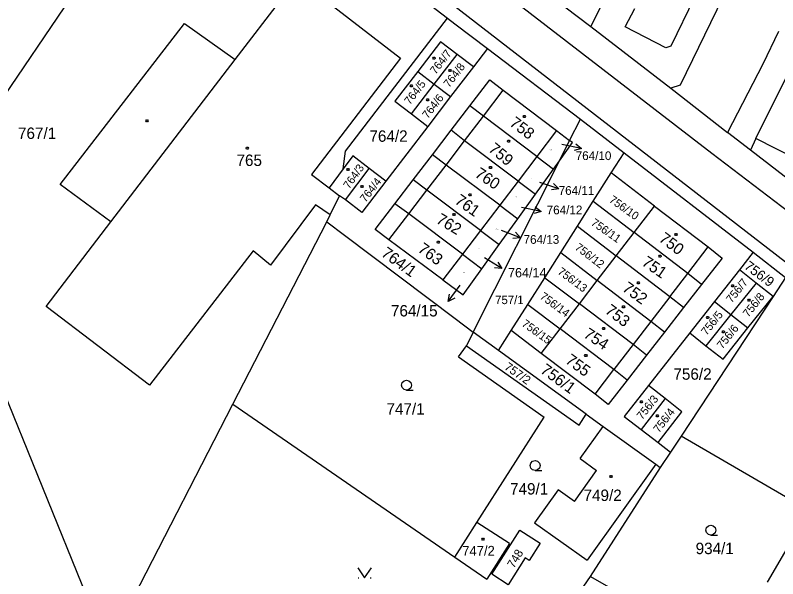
# Model space of a CAD drawing. Extents: x -621797 to -620972, y -1175539 to -1174697.
# Drawn here: x -621205.7 to -621092, y -1175296.1 to -1175212.1 of the extents above; entities that cross this region are included whole.
import ezdxf

# ---------------------------------------------------------------- set-up
doc = ezdxf.new("R2010")
doc.units = 0
for name, color, linetype in [('INZ mimo EON - nadz', 7, 'Continuous'), ('Rozvod plynu EON', 7, 'Continuous'), ('SDEL EON', 7, 'Continuous'), ('SDEL EON - popis', 7, 'Continuous'), ('Silnoproud EON', 7, 'Continuous'), ('Silnoproud EON - popis', 7, 'Continuous')]:
    doc.layers.add(name, color=color, linetype=linetype)

msp = doc.modelspace()

# ---------------------------------------------------------------- linework, layer by layer
at = {"layer": 'INZ mimo EON - nadz'}
for p, q in [((-621121.266, -1175232.014), (-621124.2, -1175231.39)), ((-621124.643, -1175238.016), (-621127.48, -1175237.04)), ((-621127.275, -1175241.364), (-621130.22, -1175240.79)), ((-621130.379, -1175245.295), (-621133.18, -1175244.22)), ((-621133.149, -1175249.836), (-621135.72, -1175248.29)), ((-621141.124, -1175254.787), (-621139.36, -1175252.36))]:
    msp.add_line(p, q, dxfattribs=at)
for points in [[(-621122.14, -1175231.317), (-621121.266, -1175232.014), (-621122.348, -1175232.295)], [(-621125.426, -1175237.218), (-621124.643, -1175238.016), (-621125.751, -1175238.164)], [(-621128.161, -1175240.682), (-621127.275, -1175241.364), (-621128.353, -1175241.663)], [(-621131.134, -1175244.47), (-621130.379, -1175245.295), (-621131.492, -1175245.403)], [(-621133.748, -1175248.892), (-621133.149, -1175249.836), (-621134.264, -1175249.749)], [(-621140.132, -1175254.272), (-621141.124, -1175254.787), (-621140.94, -1175253.684)]]:
    msp.add_lwpolyline(points, dxfattribs=at)
at = {"layer": 'Rozvod plynu EON'}
for points in [[(-621143.16, -1175218.41), (-621143.07, -1175218.56), (-621143.16, -1175218.71), (-621143.34, -1175218.71), (-621143.43, -1175218.56), (-621143.34, -1175218.41)], [(-621140.79, -1175220.22), (-621140.7, -1175220.37), (-621140.79, -1175220.52), (-621140.97, -1175220.52), (-621141.06, -1175220.37), (-621140.97, -1175220.22)], [(-621146.54, -1175222.49), (-621146.45, -1175222.64), (-621146.54, -1175222.79), (-621146.72, -1175222.79), (-621146.81, -1175222.64), (-621146.72, -1175222.49)], [(-621144.12, -1175224.61), (-621144.03, -1175224.76), (-621144.12, -1175224.91), (-621144.3, -1175224.91), (-621144.39, -1175224.76), (-621144.3, -1175224.61)], [(-621185.95, -1175227.74), (-621185.86, -1175227.89), (-621185.95, -1175228.04), (-621186.13, -1175228.04), (-621186.22, -1175227.89), (-621186.13, -1175227.74)], [(-621129.7, -1175227.06), (-621129.61, -1175227.21), (-621129.7, -1175227.36), (-621129.88, -1175227.36), (-621129.97, -1175227.21), (-621129.88, -1175227.06)], [(-621132.06, -1175230.75), (-621131.97, -1175230.9), (-621132.06, -1175231.05), (-621132.24, -1175231.05), (-621132.33, -1175230.9), (-621132.24, -1175230.75)], [(-621171.01, -1175231.8), (-621170.92, -1175231.95), (-621171.01, -1175232.1), (-621171.19, -1175232.1), (-621171.28, -1175231.95), (-621171.19, -1175231.8)], [(-621155.99, -1175234.97), (-621155.9, -1175235.12), (-621155.99, -1175235.27), (-621156.17, -1175235.27), (-621156.26, -1175235.12), (-621156.17, -1175234.97)], [(-621134.75, -1175234.66), (-621134.66, -1175234.81), (-621134.75, -1175234.96), (-621134.93, -1175234.96), (-621135.02, -1175234.81), (-621134.93, -1175234.66)], [(-621153.9, -1175237.51), (-621153.81, -1175237.66), (-621153.9, -1175237.81), (-621154.08, -1175237.81), (-621154.17, -1175237.66), (-621154.08, -1175237.51)], [(-621137.82, -1175238.72), (-621137.73, -1175238.87), (-621137.82, -1175239.02), (-621138, -1175239.02), (-621138.09, -1175238.87), (-621138, -1175238.72)], [(-621140.18, -1175241.68), (-621140.09, -1175241.83), (-621140.18, -1175241.98), (-621140.36, -1175241.98), (-621140.45, -1175241.83), (-621140.36, -1175241.68)], [(-621107.11, -1175244.63), (-621107.02, -1175244.78), (-621107.11, -1175244.93), (-621107.29, -1175244.93), (-621107.38, -1175244.78), (-621107.29, -1175244.63)], [(-621142.54, -1175245.81), (-621142.45, -1175245.96), (-621142.54, -1175246.11), (-621142.72, -1175246.11), (-621142.81, -1175245.96), (-621142.72, -1175245.81)], [(-621109.47, -1175247.88), (-621109.38, -1175248.03), (-621109.47, -1175248.18), (-621109.65, -1175248.18), (-621109.74, -1175248.03), (-621109.65, -1175247.88)], [(-621112.72, -1175251.86), (-621112.63, -1175252.01), (-621112.72, -1175252.16), (-621112.9, -1175252.16), (-621112.99, -1175252.01), (-621112.9, -1175251.86)], [(-621098.66, -1175252.29), (-621098.57, -1175252.44), (-621098.66, -1175252.59), (-621098.84, -1175252.59), (-621098.93, -1175252.44), (-621098.84, -1175252.29)], [(-621096.22, -1175254.43), (-621096.13, -1175254.58), (-621096.22, -1175254.73), (-621096.4, -1175254.73), (-621096.49, -1175254.58), (-621096.4, -1175254.43)], [(-621114.93, -1175255.41), (-621114.84, -1175255.56), (-621114.93, -1175255.71), (-621115.11, -1175255.71), (-621115.2, -1175255.56), (-621115.11, -1175255.41)], [(-621102.37, -1175257.02), (-621102.28, -1175257.17), (-621102.37, -1175257.32), (-621102.55, -1175257.32), (-621102.64, -1175257.17), (-621102.55, -1175257.02)], [(-621117.89, -1175258.66), (-621117.8, -1175258.81), (-621117.89, -1175258.96), (-621118.07, -1175258.96), (-621118.16, -1175258.81), (-621118.07, -1175258.66)], [(-621100.03, -1175259.15), (-621099.94, -1175259.3), (-621100.03, -1175259.45), (-621100.21, -1175259.45), (-621100.3, -1175259.3), (-621100.21, -1175259.15)], [(-621120.54, -1175262.64), (-621120.45, -1175262.79), (-621120.54, -1175262.94), (-621120.72, -1175262.94), (-621120.81, -1175262.79), (-621120.72, -1175262.64)], [(-621112.27, -1175269.55), (-621112.18, -1175269.7), (-621112.27, -1175269.85), (-621112.45, -1175269.85), (-621112.54, -1175269.7), (-621112.45, -1175269.55)], [(-621109.89, -1175271.63), (-621109.8, -1175271.78), (-621109.89, -1175271.93), (-621110.07, -1175271.93), (-621110.16, -1175271.78), (-621110.07, -1175271.63)], [(-621116.78, -1175280.68), (-621116.69, -1175280.83), (-621116.78, -1175280.98), (-621116.96, -1175280.98), (-621117.05, -1175280.83), (-621116.96, -1175280.68)], [(-621135.86, -1175290.03), (-621135.77, -1175290.18), (-621135.86, -1175290.33), (-621136.04, -1175290.33), (-621136.13, -1175290.18), (-621136.04, -1175290.03)]]:
    msp.add_lwpolyline(points, close=True, dxfattribs=at)
at = {"layer": 'SDEL EON'}
for p, q in [((-621154.55, -1175295.91), (-621154.45, -1175295.91)), ((-621152.75, -1175295.91), (-621152.65, -1175295.91))]:
    msp.add_line(p, q, dxfattribs=at)
for points in [[(-621147.35, -1175267.96), (-621147.73, -1175267.86), (-621148, -1175267.59), (-621148.1, -1175267.22), (-621148, -1175266.85), (-621147.73, -1175266.58), (-621147.36, -1175266.48), (-621146.99, -1175266.58), (-621146.72, -1175266.85), (-621146.62, -1175267.23), (-621146.72, -1175267.61), (-621146.99, -1175267.88), (-621147.37, -1175267.98), (-621146.37, -1175267.98)], [(-621128.18, -1175279.94), (-621128.56, -1175279.84), (-621128.83, -1175279.57), (-621128.93, -1175279.2), (-621128.83, -1175278.83), (-621128.56, -1175278.56), (-621128.19, -1175278.46), (-621127.82, -1175278.56), (-621127.55, -1175278.83), (-621127.45, -1175279.21), (-621127.55, -1175279.59), (-621127.82, -1175279.86), (-621128.2, -1175279.96), (-621127.2, -1175279.96)], [(-621101.99, -1175289.55), (-621102.37, -1175289.45), (-621102.64, -1175289.18), (-621102.74, -1175288.81), (-621102.64, -1175288.44), (-621102.37, -1175288.17), (-621102, -1175288.07), (-621101.63, -1175288.17), (-621101.36, -1175288.44), (-621101.26, -1175288.82), (-621101.36, -1175289.2), (-621101.63, -1175289.47), (-621102.01, -1175289.57), (-621101.01, -1175289.57)], [(-621154.6, -1175294.41), (-621153.6, -1175295.91), (-621152.6, -1175294.41)]]:
    msp.add_lwpolyline(points, dxfattribs=at)
at = {"layer": 'SDEL EON - popis'}
for p, q in [((-621208, -1175150.85), (-621101.85, -1175232.68)), ((-621089.77, -1175249.76), (-621211.57, -1175155.68)), ((-621104.06, -1175208.76), (-621107.98, -1175216.73)), ((-621114.77, -1175213.88), (-621113.35, -1175211.13)), ((-621108.7, -1175216.99), (-621114.77, -1175213.88)), ((-621107.98, -1175216.73), (-621108.7, -1175216.99)), ((-621191.44, -1175242.92), (-621172.9, -1175218.73)), ((-621095.27, -1175230.52), (-621090.87, -1175221.63)), ((-621135.89, -1175227.17), (-621132.93, -1175223.3)), ((-621138.69, -1175230.83), (-621135.89, -1175227.17)), ((-621141.46, -1175234.45), (-621138.69, -1175230.83)), ((-621124.56, -1175233.81), (-621122.62, -1175231.12)), ((-621122.62, -1175231.12), (-621123.04, -1175230.8)), ((-621101.85, -1175232.68), (-621058.9, -1175265.53)), ((-621144.32, -1175238.2), (-621141.46, -1175234.45)), ((-621147.03, -1175241.74), (-621144.32, -1175238.2)), ((-621149.97, -1175245.59), (-621147.03, -1175241.74)), ((-621105.45, -1175250.59), (-621102.42, -1175246.64)), ((-621108.12, -1175254.06), (-621105.45, -1175250.59)), ((-621108.12, -1175254.06), (-621110.94, -1175257.73)), ((-621110.94, -1175257.73), (-621113.59, -1175261.17)), ((-621113.59, -1175261.17), (-621116.45, -1175264.89)), ((-621119.26, -1175268.55), (-621116.45, -1175264.89))]:
    msp.add_line(p, q, dxfattribs=at)
at = {"layer": 'Silnoproud EON'}
for p, q in [((-621164.04, -1175194.97), (-621141.26, -1175212.57)), ((-621096.51, -1175201.92), (-621106.57, -1175222.57)), ((-621131.22, -1175205.15), (-621119.89, -1175213.84)), ((-621172.9, -1175218.73), (-621163.62, -1175206.69)), ((-621163.62, -1175206.69), (-621148.24, -1175218.52)), ((-621218.73, -1175240.96), (-621195.95, -1175207.41)), ((-621119.89, -1175213.84), (-621117.5, -1175209.07)), ((-621156.45, -1175232.39), (-621141.26, -1175212.57)), ((-621141.26, -1175212.57), (-621140.15, -1175213.42)), ((-621199, -1175237.34), (-621180.45, -1175213.39)), ((-621180.45, -1175213.39), (-621172.9, -1175218.73)), ((-621140.15, -1175213.42), (-621135.29, -1175217.11)), ((-621119.89, -1175213.84), (-621107.97, -1175222.99)), ((-621091.92, -1175214.56), (-621094.23, -1175219.42)), ((-621142.29, -1175216.09), (-621145.68, -1175220.51)), ((-621139.83, -1175217.97), (-621142.29, -1175216.09)), ((-621135.29, -1175217.11), (-621137.39, -1175219.85)), ((-621135.29, -1175217.11), (-621121.44, -1175227.63)), ((-621148.24, -1175218.52), (-621161.53, -1175235.85)), ((-621143.22, -1175222.39), (-621139.83, -1175217.97)), ((-621137.39, -1175219.85), (-621139.83, -1175217.97)), ((-621137.39, -1175219.85), (-621140.78, -1175224.27)), ((-621094.23, -1175219.42), (-621099.51, -1175229.63)), ((-621145.68, -1175220.51), (-621149.08, -1175224.93)), ((-621145.68, -1175220.51), (-621143.22, -1175222.39)), ((-621137.92, -1175225.62), (-621134.96, -1175221.75)), ((-621134.96, -1175221.75), (-621132.93, -1175223.3)), ((-621146.62, -1175226.81), (-621143.22, -1175222.39)), ((-621143.22, -1175222.39), (-621140.78, -1175224.27)), ((-621106.57, -1175222.57), (-621107.97, -1175222.99)), ((-621107.97, -1175222.99), (-621099.51, -1175229.63)), ((-621140.78, -1175224.27), (-621144.17, -1175228.69)), ((-621132.93, -1175223.3), (-621124.98, -1175229.33)), ((-621149.08, -1175224.93), (-621146.62, -1175226.81)), ((-621140.72, -1175229.28), (-621137.92, -1175225.62)), ((-621135.89, -1175227.17), (-621137.92, -1175225.62)), ((-621146.62, -1175226.81), (-621144.17, -1175228.69)), ((-621127.92, -1175233.19), (-621135.89, -1175227.17)), ((-621123.04, -1175230.8), (-621121.44, -1175227.63)), ((-621121.44, -1175227.63), (-621114.94, -1175232.63)), ((-621144.17, -1175228.69), (-621150.44, -1175236.87)), ((-621143.5, -1175232.91), (-621140.72, -1175229.28)), ((-621138.69, -1175230.83), (-621140.72, -1175229.28)), ((-621124.98, -1175229.33), (-621127.92, -1175233.19)), ((-621124.98, -1175229.33), (-621123.04, -1175230.8)), ((-621096.09, -1175232.26), (-621099.51, -1175229.63)), ((-621130.71, -1175236.84), (-621138.69, -1175230.83)), ((-621124.56, -1175233.81), (-621123.04, -1175230.8)), ((-621095.27, -1175230.52), (-621096.09, -1175232.26)), ((-621086.53, -1175234.94), (-621095.27, -1175230.52)), ((-621076.83, -1175247.04), (-621096.09, -1175232.26)), ((-621156.79, -1175235), (-621156.45, -1175232.39)), ((-621155.37, -1175233.08), (-621156.79, -1175235)), ((-621152.9, -1175234.98), (-621155.37, -1175233.08)), ((-621146.38, -1175236.67), (-621143.5, -1175232.91)), ((-621141.46, -1175234.45), (-621143.5, -1175232.91)), ((-621127.92, -1175233.19), (-621130.71, -1175236.84)), ((-621127.92, -1175233.19), (-621125.45, -1175235.05)), ((-621116.83, -1175235.61), (-621114.94, -1175232.63)), ((-621114.94, -1175232.63), (-621095.7, -1175247.45)), ((-621133.47, -1175240.45), (-621141.46, -1175234.45)), ((-621137.44, -1175259.35), (-621124.56, -1175233.81)), ((-621125.45, -1175235.05), (-621124.56, -1175233.81)), ((-621156.79, -1175235), (-621158.91, -1175237.85)), ((-621156.46, -1175239.63), (-621152.9, -1175234.98)), ((-621150.44, -1175236.87), (-621152.9, -1175234.98)), ((-621128.13, -1175238.78), (-621125.45, -1175235.05)), ((-621119.52, -1175239.84), (-621116.83, -1175235.61)), ((-621110.41, -1175240.56), (-621116.83, -1175235.61)), ((-621161.53, -1175235.85), (-621158.91, -1175237.85)), ((-621150.44, -1175236.87), (-621154, -1175241.51)), ((-621149.09, -1175240.21), (-621146.38, -1175236.67)), ((-621144.32, -1175238.2), (-621146.38, -1175236.67)), ((-621130.71, -1175236.84), (-621133.47, -1175240.45)), ((-621130.71, -1175236.84), (-621128.13, -1175238.78)), ((-621191.44, -1175242.92), (-621199, -1175237.34)), ((-621158.91, -1175237.85), (-621157.33, -1175239.05)), ((-621158.72, -1175241.87), (-621157.33, -1175239.05)), ((-621156.46, -1175239.63), (-621157.33, -1175239.05)), ((-621136.32, -1175244.18), (-621144.32, -1175238.2)), ((-621130.78, -1175242.48), (-621128.13, -1175238.78)), ((-621154, -1175241.51), (-621156.46, -1175239.63)), ((-621152.04, -1175244.07), (-621149.09, -1175240.21)), ((-621147.03, -1175241.74), (-621149.09, -1175240.21)), ((-621121.88, -1175243.57), (-621119.52, -1175239.84)), ((-621119.52, -1175239.84), (-621113.44, -1175244.5)), ((-621160.92, -1175240.4), (-621167.63, -1175249.36)), ((-621158.72, -1175241.87), (-621160.92, -1175240.4)), ((-621133.47, -1175240.45), (-621136.32, -1175244.18)), ((-621133.47, -1175240.45), (-621130.78, -1175242.48)), ((-621113.44, -1175244.5), (-621110.41, -1175240.56)), ((-621110.41, -1175240.56), (-621102.42, -1175246.64)), ((-621159.22, -1175242.9), (-621158.72, -1175241.87)), ((-621139.01, -1175247.71), (-621147.03, -1175241.74)), ((-621133.53, -1175246.29), (-621130.78, -1175242.48)), ((-621201.05, -1175255.51), (-621191.44, -1175242.92)), ((-621173.23, -1175270.07), (-621159.22, -1175242.9)), ((-621159.22, -1175242.9), (-621156.58, -1175244.89)), ((-621124.38, -1175247.5), (-621121.88, -1175243.57)), ((-621121.88, -1175243.57), (-621116.11, -1175247.98)), ((-621149.97, -1175245.59), (-621152.04, -1175244.07)), ((-621136.32, -1175244.18), (-621139.01, -1175247.71)), ((-621136.32, -1175244.18), (-621133.53, -1175246.29)), ((-621116.11, -1175247.98), (-621113.44, -1175244.5)), ((-621105.45, -1175250.59), (-621113.44, -1175244.5)), ((-621156.58, -1175244.89), (-621140.11, -1175257.29)), ((-621141.94, -1175251.55), (-621149.97, -1175245.59)), ((-621136.12, -1175249.9), (-621133.53, -1175246.29)), ((-621102.42, -1175246.64), (-621100.32, -1175248.31)), ((-621170.21, -1175247.22), (-621185.65, -1175267.22)), ((-621167.63, -1175249.36), (-621170.21, -1175247.22)), ((-621139.01, -1175247.71), (-621141.94, -1175251.55)), ((-621139.01, -1175247.71), (-621136.12, -1175249.9)), ((-621126.74, -1175251.23), (-621124.38, -1175247.5)), ((-621124.38, -1175247.5), (-621118.94, -1175251.66)), ((-621118.94, -1175251.66), (-621116.11, -1175247.98)), ((-621108.12, -1175254.06), (-621116.11, -1175247.98)), ((-621095.7, -1175247.45), (-621097.75, -1175250.06)), ((-621095.7, -1175247.45), (-621090.85, -1175251.18)), ((-621100.32, -1175248.31), (-621103.38, -1175252.24)), ((-621138.92, -1175253.79), (-621136.12, -1175249.9)), ((-621097.75, -1175250.06), (-621101.45, -1175254.76)), ((-621095.26, -1175252.02), (-621097.75, -1175250.06)), ((-621141.94, -1175251.55), (-621138.92, -1175253.79)), ((-621129.27, -1175255.21), (-621126.74, -1175251.23)), ((-621126.74, -1175251.23), (-621121.59, -1175255.11)), ((-621121.59, -1175255.11), (-621118.94, -1175251.66)), ((-621110.94, -1175257.73), (-621118.94, -1175251.66)), ((-621103.38, -1175252.24), (-621105.45, -1175250.59)), ((-621090.85, -1175251.18), (-621092.72, -1175254.02)), ((-621103.38, -1175252.24), (-621106.06, -1175255.69)), ((-621095.26, -1175252.02), (-621099, -1175256.69)), ((-621092.72, -1175254.02), (-621095.26, -1175252.02)), ((-621124.46, -1175258.84), (-621121.59, -1175255.11)), ((-621113.59, -1175261.17), (-621121.59, -1175255.11)), ((-621106.06, -1175255.69), (-621108.12, -1175254.06)), ((-621092.72, -1175254.02), (-621106.4, -1175274.82)), ((-621101.45, -1175254.76), (-621105.14, -1175259.45)), ((-621101.45, -1175254.76), (-621099, -1175256.69)), ((-621096.46, -1175258.69), (-621092.72, -1175254.02)), ((-621185.65, -1175267.22), (-621201.05, -1175255.51)), ((-621131.74, -1175259.1), (-621129.27, -1175255.21)), ((-621129.27, -1175255.21), (-621124.46, -1175258.84)), ((-621106.06, -1175255.69), (-621108.91, -1175259.35)), ((-621140.11, -1175257.29), (-621137.44, -1175259.35)), ((-621099, -1175256.69), (-621102.73, -1175261.35)), ((-621099, -1175256.69), (-621096.46, -1175258.69)), ((-621108.91, -1175259.35), (-621110.94, -1175257.73)), ((-621137.44, -1175259.35), (-621138.41, -1175261.37)), ((-621133.63, -1175262.08), (-621137.44, -1175259.35)), ((-621133.63, -1175262.08), (-621131.74, -1175259.1)), ((-621127.27, -1175262.51), (-621131.74, -1175259.1)), ((-621127.27, -1175262.51), (-621124.46, -1175258.84)), ((-621116.45, -1175264.89), (-621124.46, -1175258.84)), ((-621108.91, -1175259.35), (-621111.57, -1175262.78)), ((-621105.14, -1175259.45), (-621111.29, -1175267.27)), ((-621105.14, -1175259.45), (-621102.73, -1175261.35)), ((-621100.15, -1175263.38), (-621096.46, -1175258.69)), ((-621139.61, -1175263.01), (-621138.41, -1175261.37)), ((-621138.41, -1175261.37), (-621121.63, -1175273.17)), ((-621111.57, -1175262.78), (-621113.59, -1175261.17)), ((-621102.73, -1175261.35), (-621100.15, -1175263.38)), ((-621139.61, -1175263.01), (-621126.85, -1175271.98)), ((-621120.58, -1175271.55), (-621133.63, -1175262.08)), ((-621119.26, -1175268.55), (-621127.27, -1175262.51)), ((-621111.57, -1175262.78), (-621114.45, -1175266.48)), ((-621114.45, -1175266.48), (-621116.45, -1175264.89)), ((-621208.28, -1175266.18), (-621191.91, -1175306.3)), ((-621114.45, -1175266.48), (-621117.28, -1175270.13)), ((-621111.29, -1175267.27), (-621114.94, -1175271.91)), ((-621108.8, -1175269.23), (-621111.29, -1175267.27)), ((-621117.28, -1175270.13), (-621119.26, -1175268.55)), ((-621108.8, -1175269.23), (-621112.39, -1175273.85)), ((-621106.3, -1175271.2), (-621108.8, -1175269.23)), ((-621188.79, -1175300.25), (-621173.23, -1175270.07)), ((-621173.23, -1175270.07), (-621140.17, -1175292.83)), ((-621136.87, -1175287.66), (-621126.85, -1175271.98)), ((-621121.63, -1175273.17), (-621120.58, -1175271.55)), ((-621120.58, -1175271.55), (-621118.03, -1175273.39)), ((-621114.94, -1175271.91), (-621112.39, -1175273.85)), ((-621109.87, -1175275.77), (-621106.3, -1175271.2)), ((-621121.46, -1175278.17), (-621118.03, -1175273.39)), ((-621118.03, -1175273.39), (-621110.22, -1175279.01)), ((-621112.39, -1175273.85), (-621109.87, -1175275.77)), ((-621106.4, -1175274.82), (-621108, -1175277.19)), ((-621087.51, -1175285.82), (-621106.4, -1175274.82)), ((-621109.87, -1175275.77), (-621108, -1175277.19)), ((-621108, -1175277.19), (-621109.55, -1175279.49)), ((-621121.46, -1175278.17), (-621119.03, -1175279.92)), ((-621122.33, -1175284.54), (-621119.03, -1175279.92)), ((-621110.22, -1175279.01), (-621120.44, -1175293.31)), ((-621109.55, -1175279.49), (-621119.98, -1175295.73)), ((-621110.22, -1175279.01), (-621109.55, -1175279.49)), ((-621124.77, -1175282.8), (-621128.26, -1175287.71)), ((-621122.33, -1175284.54), (-621124.77, -1175282.8)), ((-621140.17, -1175292.83), (-621136.87, -1175287.66)), ((-621132, -1175290.8), (-621136.87, -1175287.66)), ((-621128.26, -1175287.71), (-621120.44, -1175293.31)), ((-621134.64, -1175295.37), (-621130.47, -1175288.84)), ((-621130.47, -1175288.84), (-621127.43, -1175290.78)), ((-621089.65, -1175289.79), (-621093.58, -1175296.56)), ((-621132, -1175290.8), (-621135.4, -1175296.12)), ((-621127.43, -1175290.78), (-621129.06, -1175293.34)), ((-621140.17, -1175292.83), (-621135.4, -1175296.12)), ((-621129.65, -1175292.96), (-621132.21, -1175296.94)), ((-621129.06, -1175293.34), (-621129.65, -1175292.96)), ((-621132.21, -1175296.94), (-621134.64, -1175295.37)), ((-621119.98, -1175295.73), (-621125.2, -1175303.13)), ((-621089.12, -1175313.15), (-621119.98, -1175295.73))]:
    msp.add_line(p, q, dxfattribs=at)

# ---------------------------------------------------------------- texts
at = {"layer": 'INZ mimo EON - nadz'}
for s, height, p in [('764/10', 1.3, (-621122.138, -1175233.71)), ('764/11', 1.3, (-621124.678, -1175238.89)), ('764/12', 1.3, (-621126.468, -1175241.79)), ('764/13', 1.3, (-621129.908, -1175246.18)), ('764/14', 1.4, (-621132.224, -1175251.18)), ('764/15', 1.7, (-621149.673, -1175257))]:
    msp.add_text(s, height=height, dxfattribs=at).set_placement(p)
at = {"layer": 'Silnoproud EON - popis'}
for s, height, rotation, p in [('764/7', 1.2, 52.19646, (-621143.017, -1175221.038)), ('764/8', 1.2, 52.19646, (-621141.007, -1175223.008)), ('764/5', 1.2, 52.19646, (-621146.857, -1175225.568)), ('764/6', 1.2, 52.19646, (-621144.187, -1175227.648)), ('758', 1.7, 323.0909, (-621132.13, -1175228.463)), ('759', 1.7, 320.398, (-621135.257, -1175232.281)), ('764/10', 0.1, 7.21927, (-621126.096, -1175232.278)), ('764/3', 1.19, 54.60288, (-621155.914, -1175238.105)), ('760', 1.7, 326.70054, (-621137.312, -1175236.11)), ('764/4', 1.2, 52.19646, (-621153.467, -1175240.108)), ('761', 1.7, 324.92437, (-621140.296, -1175240.056)), ('756/10', 1.2, 324.58059, (-621117.263, -1175239.867)), ('762', 1.7, 329.39344, (-621143.076, -1175242.991)), ('756/11', 1.2, 325.21084, (-621119.962, -1175243.296)), ('750', 1.7, 323.0909, (-621109.86, -1175245.683)), ('763', 1.7, 324.00763, (-621145.808, -1175247.25)), ('756/12', 1.2, 322.46065, (-621122.357, -1175246.922)), ('764/1', 1.7, 324.00763, (-621151.248, -1175247.89)), ('751', 1.7, 325.26814, (-621112.425, -1175249.265)), ('756/9', 1.45, 323.20549, (-621097.13, -1175249.783)), ('756/13', 1.2, 323.66386, (-621124.945, -1175250.559)), ('756/7', 1.2, 51.27972, (-621098.895, -1175255.089)), ('752', 1.7, 324.00763, (-621115.318, -1175253.08)), ('756/14', 1.21, 323.77845, (-621127.594, -1175254.25)), ('756/8', 1.2, 51.27972, (-621096.405, -1175257.219)), ('753', 1.7, 323.0909, (-621117.9, -1175256.393)), ('756/5', 1.2, 51.27972, (-621102.625, -1175259.909)), ('756/15', 1.2, 324.35141, (-621130.284, -1175258.328)), ('756/6', 1.2, 51.27972, (-621100.275, -1175261.939)), ('754', 1.7, 326.70054, (-621121.102, -1175260)), ('755', 1.7, 324.00763, (-621123.808, -1175263.82)), ('757/2', 1.27, 324.92437, (-621132.885, -1175264.772)), ('756/1', 1.7, 324.00763, (-621127.538, -1175265.27)), ('756/3', 1.2, 51.6235, (-621112.226, -1175272.469)), ('756/4', 1.2, 52.59753, (-621109.728, -1175274.427)), ('747/2', 1.45, 0.40107, (-621139.047, -1175292.645)), ('748', 1.27, 58.72818, (-621131.36, -1175294.585))]:
    msp.add_text(s, height=height, rotation=rotation, dxfattribs=at).set_placement(p)
for s, height, p in [('767/1', 1.7, (-621205.265, -1175230.57)), ('764/2', 1.7, (-621152.883, -1175230.99)), ('765', 1.7, (-621172.693, -1175234.59)), ('764/11', 0.1, (-621128.846, -1175236.57)), ('764/12', 0.1, (-621131.166, -1175239.26)), ('764/13', 0.1, (-621134.076, -1175244.01)), ('764/14', 0.1, (-621136.656, -1175247.02)), ('764/15', 0.1, (-621139.036, -1175250.51)), ('757/1', 1.27, (-621134.15, -1175255.165)), ('756/2', 1.7, (-621107.573, -1175266.42)), ('747/1', 1.7, (-621150.345, -1175271.62)), ('749/1', 1.7, (-621131.925, -1175283.52)), ('749/2', 1.7, (-621120.967, -1175284.48)), ('934/1', 1.7, (-621104.263, -1175292.39))]:
    msp.add_text(s, height=height, dxfattribs=at).set_placement(p)

doc.saveas('drawing.dxf')
